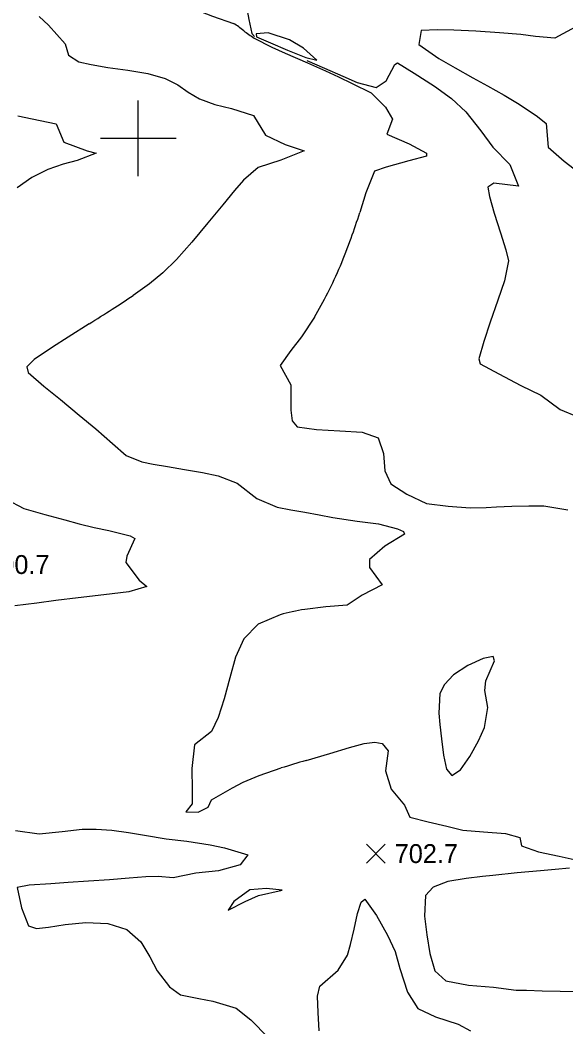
# Model space of a CAD drawing. Extents: x 2566079 to 2571326, y 424054 to 426896.
# Drawn here: x 2567906 to 2568340, y 425294 to 426094 of the extents above; entities that cross this region are included whole.
import ezdxf

# ---------------------------------------------------------------- set-up
doc = ezdxf.new("R2010")
doc.units = 0
for name, color, linetype in [('Contour_ADS_Major', 7, 'Continuous'), ('Contour_ADS_Minor', 7, 'Continuous'), ('Contour_ADS_Spot_Elevation', 7, 'Continuous'), ('Contour_ADS_Tick', 7, 'Continuous')]:
    doc.layers.add(name, color=color, linetype=linetype)

# ---------------------------------------------------------------- blocks, each defined once
blk = doc.blocks.new('S890')
at = {"layer": 'Contour_ADS_Tick'}
for p, q in [((0, -0.5), (0, 0.5)), ((-0.5, 0), (0.5, 0))]:
    blk.add_line(p, q, dxfattribs=at)
blk = doc.blocks.new('S750')
at = {"layer": 'Contour_ADS_Spot_Elevation'}
for p, q in [((-0.5, 0.498), (0.5, -0.498)), ((-0.498, -0.5), (0.498, 0.5))]:
    blk.add_line(p, q, dxfattribs=at)

msp = doc.modelspace()

# ---------------------------------------------------------------- linework, layer by layer
at = {"layer": 'Contour_ADS_Major'}
msp.add_lwpolyline([(2568093.71, 426082.93), (2568093.8, 426080.54), (2568104.91, 426075.71), (2568118.61, 426069.89), (2568133.06, 426064.21), (2568141.78, 426061.91), (2568131.32, 426071.67), (2568120.04, 426078.22), (2568103.2, 426083.84), (2568093.71, 426082.93)], close=True, dxfattribs=at)
msp.add_lwpolyline([(2568346.97, 426088.24), (2568330.84, 426079.5), (2568315.62, 426080.72), (2568303.77, 426082.37), (2568286.99, 426083.85), (2568268.08, 426085.04), (2568250.68, 426085.85), (2568237.72, 426086.25), (2568224.65, 426085.5), (2568222.9, 426074.4), (2568238.84, 426063.45), (2568251.73, 426055.93), (2568265.67, 426048.03), (2568277.39, 426041.53), (2568290.52, 426034.14), (2568302.5, 426027.1), (2568317.18, 426017.17), (2568323.84, 426011.61), (2568325.43, 425992.89), (2568338.34, 425981.76), (2568349.54, 425973.04)], dxfattribs=at)
at = {"layer": 'Contour_ADS_Minor'}
for points in [[(2567859.45, 426216.94), (2567874.95, 426210.2), (2567886.63, 426205.19), (2567902.82, 426197.6), (2567917.72, 426189.39), (2567934.14, 426179.74), (2567944.05, 426172.71), (2567952.93, 426166.17), (2567963.36, 426157.73), (2567972.2, 426148.83), (2567979.01, 426134.04), (2567980.77, 426124.79), (2567995.12, 426120.38), (2568011.95, 426114.73), (2568025.42, 426109.65), (2568041.33, 426103.97), (2568059.03, 426096.92), (2568075.56, 426091.2)], [(2568103.71, 426167.38), (2568085.34, 426174.47), (2568080.21, 426175.93), (2568067.94, 426170.87), (2568058.62, 426167.96), (2568047.09, 426166.38), (2568034.12, 426167.02), (2568021.57, 426168.85), (2568005.8, 426170.42), (2568002.32, 426167.98), (2568010.09, 426161.13), (2568021.18, 426155.22), (2568035.15, 426148.01), (2568048.9, 426140.9), (2568059.94, 426135.01), (2568073.69, 426126.43), (2568084.81, 426110.25), (2568087.74, 426094.4), (2568090.25, 426083.3), (2568092.24, 426080.74)], [(2567921.34, 426096.73), (2567928.79, 426089.82), (2567941.9, 426074.96), (2567944.65, 426066.1), (2567952.82, 426060.82), (2567962.67, 426058.48), (2567975.87, 426056.26), (2567991.57, 426054.04), (2568007.57, 426051.33), (2568021.38, 426047.57), (2568031.37, 426042.45), (2568039.54, 426036.68), (2568048.74, 426031.25), (2568060.88, 426026.9), (2568073.93, 426023.52), (2568091.52, 426018.18), (2568101.01, 426002.5), (2568116.62, 425995.04), (2568131.84, 425989.99), (2568113.22, 425982.72), (2568095.17, 425976.85), (2568083.58, 425966.79), (2568076.48, 425958.49), (2568067.06, 425947.09), (2568055.29, 425932.72), (2568042.47, 425917.41), (2568030.25, 425903.62), (2568019.61, 425893.04), (2568008.93, 425884.28), (2567995.92, 425875.17)], [(2568091.96, 426079.6), (2568106.05, 426072.47), (2568116.79, 426067.51), (2568134.41, 426059.89), (2568148.7, 426053.52), (2568158.96, 426048.8), (2568170.01, 426043.62), (2568185, 426036.09), (2568196.24, 426024.67), (2568201.97, 426015.26), (2568197.5, 426003.22), (2568215.22, 425995.6), (2568228.83, 425988.1), (2568228.82, 425985.87), (2568214.8, 425982.13), (2568196.91, 425977.05), (2568187.49, 425973.93), (2568180.86, 425956.72), (2568175.9, 425940.93)], [(2568133.8, 426061.72), (2568147.94, 426055.61), (2568162.35, 426049.31), (2568173.87, 426044.3), (2568189.02, 426040.4), (2568197, 426045.51), (2568203.74, 426058.67), (2568205.98, 426060.01), (2568219.18, 426051.74), (2568235.3, 426041.37), (2568248.74, 426031.68), (2568260.09, 426021.02), (2568272.13, 426006.02), (2568281.69, 425992.81), (2568295.03, 425979.27), (2568301.96, 425961.86), (2568282.49, 425964.41), (2568277.72, 425961.24), (2568278.91, 425953.68), (2568282.73, 425940.44), (2568287.73, 425924.84), (2568292.06, 425911.3), (2568294.17, 425902.74), (2568290.79, 425886.66), (2568285.6, 425871.52), (2568279.6, 425853.89), (2568274.5, 425838.59), (2568270.56, 425824.82), (2568271.52, 425820.76), (2568286.5, 425812.96), (2568303.87, 425803.78), (2568319.67, 425795.87), (2568335.04, 425784.56), (2568349.08, 425778.76)], [(2567904.25, 426017.83), (2567915.64, 426015.39), (2567934.79, 426011.36), (2567940.89, 425996.96), (2567959.28, 425990.16), (2567966.67, 425988.09), (2567951.43, 425982.26), (2567940.45, 425979.36), (2567928.11, 425975.11), (2567915.53, 425968.98), (2567903.71, 425960.74)], [(2567960.95, 425852.54), (2567944.33, 425842), (2567931.77, 425834.01), (2567917.17, 425824.18), (2567911.48, 425818.57), (2567912.49, 425814.02), (2567925.04, 425803.2), (2567938.15, 425792.46), (2567953.11, 425780.15), (2567966.19, 425769.24), (2567979.39, 425757.51), (2567990.31, 425748.1), (2568002.79, 425743.12), (2568011.78, 425741.21), (2568023.13, 425739.25), (2568036.81, 425736.99), (2568050.98, 425734.47), (2568063.36, 425731.84), (2568078.53, 425726.19), (2568094.06, 425713.85), (2568110.42, 425707.03), (2568121.04, 425704.89), (2568132.37, 425702.97), (2568143.72, 425700.88), (2568154.65, 425698.81), (2568173.94, 425695.93), (2568190.68, 425693.82), (2568206, 425689.92), (2568210.53, 425687.68), (2568211.4, 425685.52), (2568195.72, 425676.05), (2568183.72, 425665.36), (2568183.65, 425659.2), (2568193.64, 425645.41), (2568177.81, 425637.15), (2568165.93, 425629.3), (2568148.84, 425627.78), (2568132.21, 425625.78)], [(2568139.89, 425857.97), (2568129.74, 425842.4), (2568121.13, 425831.53), (2568112.67, 425819.55), (2568121.04, 425804.13), (2568121.22, 425784.16), (2568122.18, 425775.61), (2568126.25, 425770.89), (2568141.44, 425768.65), (2568160.11, 425767.7), (2568177.86, 425766.64), (2568190.4, 425762.14), (2568194.81, 425749.61), (2568195.83, 425735.97), (2568200.7, 425725.46), (2568213.17, 425717.25), (2568229.04, 425709.95), (2568246.25, 425707.79), (2568263.67, 425706.41), (2568276.27, 425706.71), (2568284.62, 425707.22), (2568296.61, 425707.71), (2568310.1, 425708.03), (2568322.06, 425708.03), (2568341.26, 425704.85)], [(2567895.16, 425713.28), (2567909.11, 425705.91), (2567925.67, 425701.26), (2567941.62, 425697.03), (2567952.99, 425693.9), (2567965.05, 425690.86), (2567976.55, 425688.38), (2567993.55, 425684.31), (2567997.26, 425682.13), (2567991.03, 425668), (2567990.16, 425663.09), (2568000.76, 425649.07), (2568006.7, 425644.09), (2567992.54, 425639.8), (2567979.28, 425638.29), (2567968.11, 425636.97), (2567952.15, 425635), (2567934.51, 425632.79), (2567919.35, 425630.89), (2567901.89, 425628.69)], [(2568112.62, 425621.64), (2568095.22, 425614.17), (2568083.88, 425602.58), (2568077.28, 425587.86), (2568072.82, 425571.41), (2568068.32, 425554.75), (2568063.43, 425539.87), (2568058.23, 425528.85), (2568044.52, 425518.37), (2568042.52, 425499.51), (2568042.86, 425482.41), (2568042.9, 425471.33), (2568037.78, 425465.1), (2568047.54, 425464.75), (2568055.4, 425468.78), (2568058.21, 425474.69), (2568074.96, 425484.18), (2568083.42, 425488.66), (2568095.99, 425493.99), (2568113.44, 425499.89)], [(2568133.3, 425505.89), (2568152.26, 425511.49), (2568167.65, 425516.17), (2568179.35, 425519.37), (2568187.84, 425520.51), (2568193.62, 425519.29), (2568198.53, 425513.41), (2568196.48, 425497.64), (2568200.77, 425483.14), (2568211.45, 425470.33), (2568215.77, 425460.96), (2568230.27, 425457.03), (2568245.07, 425453.65), (2568257.7, 425450.49), (2568274.26, 425449.16), (2568291.71, 425447.77), (2568303.08, 425444.73), (2568304.39, 425438), (2568318.01, 425433.23), (2568334.35, 425429.88), (2568351.01, 425426.16)], [(2567902.37, 425450.16), (2567921.32, 425447.49), (2567939.67, 425449.58), (2567955.54, 425451.24), (2567966.45, 425451.26), (2567978.88, 425450.45), (2567992.22, 425448.74), (2568004.97, 425446.64), (2568022.27, 425443.7), (2568038.63, 425441.85), (2568056.97, 425438.74), (2568068.54, 425436.51), (2568087.11, 425431), (2568080.91, 425423.08), (2568063.64, 425418.1), (2568045.73, 425416.29), (2568027.79, 425412.53), (2568015.89, 425413.78), (2568006.12, 425413.39), (2567992.82, 425412.4), (2567977.17, 425411.15), (2567960.44, 425409.93), (2567944.31, 425408.86), (2567930.5, 425407.97), (2567913.35, 425406.75), (2567903.67, 425404.85), (2567907.29, 425388.71), (2567912.83, 425374.45), (2567919.21, 425372.47), (2567928.81, 425373.51), (2567941.95, 425375.69)], [(2568342.61, 425420.39), (2568331.07, 425419.36), (2568319.56, 425418.31), (2568300.86, 425416.49), (2568281.59, 425414.46), (2568273.39, 425413.63), (2568260.46, 425412.22), (2568245.98, 425409.64), (2568234.15, 425405.21), (2568228.08, 425398.55), (2568227.25, 425382.26), (2568229.28, 425367.45), (2568231.54, 425352.56), (2568235.53, 425338.83), (2568244.24, 425330.89), (2568262.28, 425327.34), (2568282.14, 425325.73), (2568300.07, 425323.54), (2568308.33, 425323.34), (2568320.69, 425323.03), (2568335.04, 425322.66), (2568348.58, 425322.3)], [(2568143.6, 425291.05), (2568142.82, 425305.57), (2568142.24, 425318.59), (2568144.25, 425326.7), (2568158.76, 425339.27), (2568166.29, 425351.31), (2568168.68, 425359.69), (2568171.34, 425371.78), (2568174.17, 425384.36), (2568177.07, 425393.34), (2568179.94, 425395.79), (2568189.22, 425382.64), (2568197.96, 425367.03), (2568203.98, 425354.11), (2568207.65, 425340.72), (2568213.88, 425321.96), (2568221.97, 425308.75), (2568235.99, 425302.3), (2568254, 425296.54), (2568263.75, 425291.21)], [(2567941.95, 425375.69), (2567958.44, 425377.19), (2567975.81, 425376.35), (2567991.03, 425371.53), (2568001.89, 425361.9), (2568009.28, 425349.89), (2568014.92, 425338.73), (2568024.8, 425326.12), (2568033.65, 425319.85), (2568048.16, 425316.75), (2568059.29, 425314.67), (2568077.83, 425309.1), (2568089.52, 425299.83), (2568103.09, 425285.78)]]:
    msp.add_lwpolyline(points, dxfattribs=at)
for points in [[(2568275.98, 425569.21), (2568282.91, 425584.93), (2568281.87, 425588.56), (2568273.83, 425586.85), (2568261.85, 425581.19), (2568250.45, 425573.76), (2568243.16, 425566.31), (2568239.62, 425558.99), (2568238.62, 425543.52), (2568239.49, 425534.33), (2568240.76, 425523.16), (2568242.31, 425510.12), (2568244.82, 425498.85), (2568249.17, 425493.91), (2568255.8, 425498.32), (2568263.42, 425509.03), (2568270.26, 425521.48), (2568274.9, 425532.02), (2568277.57, 425547.81), (2568275.2, 425561.55), (2568275.98, 425569.21)], [(2568101.87, 425404.07), (2568088.52, 425403.11), (2568075.97, 425393.86), (2568071.3, 425386.94), (2568084.79, 425393.76), (2568095.51, 425398.57), (2568114.32, 425402.91), (2568101.87, 425404.07)]]:
    msp.add_lwpolyline(points, close=True, dxfattribs=at)
for centre, radius, start, end in [((2568041.38, 426034.19), 66.47, 50.39476, 59.0604), ((2568158.26, 426182.04), 122.02, 232.36882, 237.08634), ((2567499.17, 426158.28), 710.78, 340.47653, 342.19446), ((2567765.77, 426064.67), 428.23, 337.19918, 340.3601), ((2567838.77, 426035.88), 349.77, 333.02794, 336.91199), ((2567316.7, 426892.78), 1223.47, 302.78474, 303.72164), ((2567874.89, 426016.43), 308.76, 329.1215, 333.20442), ((2566139.04, 428722.68), 3399.57, 302.4065, 302.77136), ((2568154.19, 425473.35), 154, 98.20561, 105.66014), ((2568681.61, 423655.12), 1930.29, 106.50244, 107.11825)]:
    msp.add_arc(centre, radius, start, end, dxfattribs=at)

# ---------------------------------------------------------------- block references
at = {"layer": 'Contour_ADS_Spot_Elevation', "xscale": 15, "yscale": 15}
msp.add_blockref('S750', (2568188.7, 425431.9), dxfattribs=at)
at = {"layer": 'Contour_ADS_Tick', "xscale": 60, "yscale": 60}
msp.add_blockref('S890', (2568000, 426000), dxfattribs=at)

# ---------------------------------------------------------------- texts
at = {"layer": 'Contour_ADS_Spot_Elevation'}
for s, p in [('700.7', (2567879.26, 425653.96)), ('702.7', (2568203.7, 425424.4))]:
    msp.add_text(s, height=15, dxfattribs=at).set_placement(p)

doc.saveas('drawing.dxf')
